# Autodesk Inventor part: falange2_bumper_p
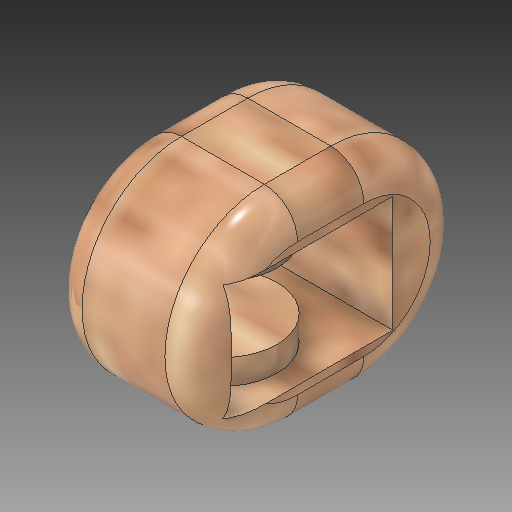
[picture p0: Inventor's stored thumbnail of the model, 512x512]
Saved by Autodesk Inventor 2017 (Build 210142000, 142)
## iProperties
Created: 2017-05
Part Number: falange2_bumper_p
Material: Generic
Document SubType Name: Modeling
Designer: alez_
Density: 1 g/cm^3
Appearance: Default
Author: alez_
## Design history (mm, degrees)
derived "Falange_2_bumper.ipt" dims "d0" = 9
feature "Solid1::Falange_2_bumper.ipt" dims "d0" = 9
tag "TaggingFeature1"
body "Solid1"
